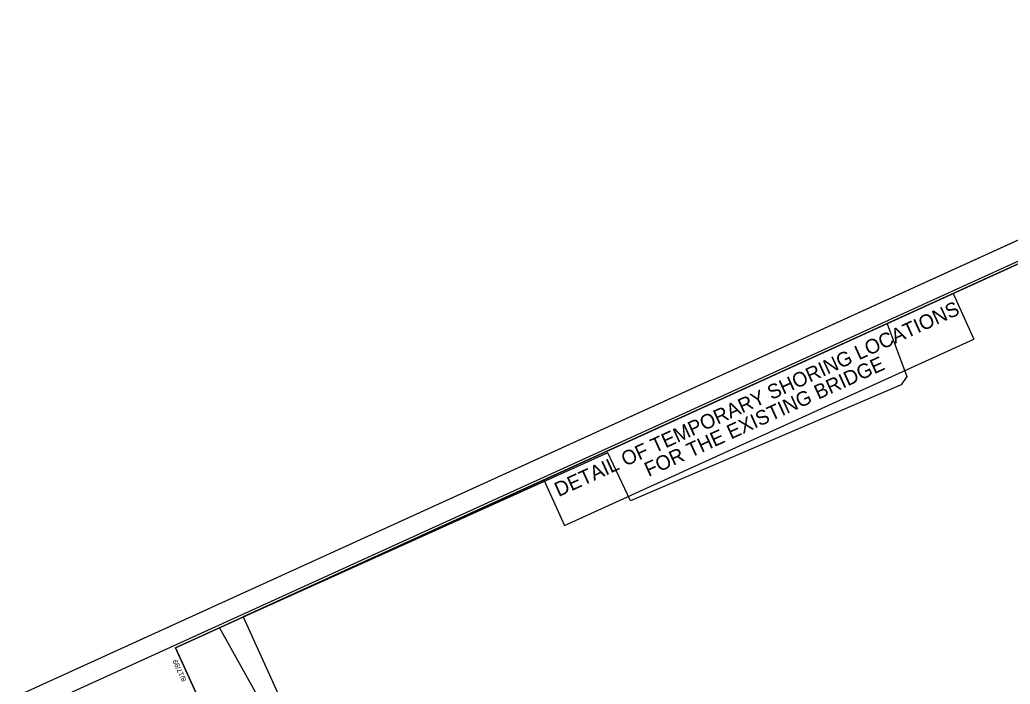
# Model space of a CAD drawing. Extents: x 2247910 to 2249896, y 662531 to 664266.
# Drawn here: x 2247910 to 2248933, y 663539 to 664226 of the extents above; entities that cross this region are included whole.
import ezdxf

# ---------------------------------------------------------------- set-up
doc = ezdxf.new("R2010")
doc.units = 0
for name, color, linetype in [('Prop Dimension', 7, 'Continuous'), ('Sheet Clip Boundary CELL', 7, 'Continuous'), ('Sheet Cutting Line CELL', 7, 'Continuous'), ('Sheet Layout Plan Border', 7, 'Continuous'), ('Sheet Plan CELL', 7, 'Continuous'), ('Sheet Plan Layout CELL', 7, 'Continuous'), ('Sheet Plot Border Inside CELL', 7, 'Continuous'), ('Sheet Plot Border Outside CELL', 7, 'Continuous')]:
    doc.layers.add(name, color=color, linetype=linetype)

msp = doc.modelspace()

# ---------------------------------------------------------------- linework, layer by layer
at = {"layer": 'Sheet Clip Boundary CELL'}
msp.add_lwpolyline([(2248241.7, 663371.1), (2248489.8, 662824.8), (2248551.2, 662641.6), (2248585.9, 662667.3), (2249638.1, 663136.9), (2249825.2, 663222.1), (2249759.4, 663344.8), (2249697.6, 663317.2), (2249673.4, 663362.4), (2249425.3, 663908.7), (2249477.5, 663985.1), (2249333.3, 663919.4), (2249245.6, 664111.9), (2248806.2, 663911.3), (2248826.4, 663857), (2248820.5, 663848.4), (2248540.8, 663728.2), (2248517.3, 663777.9), (2248115.8, 663597.1)], close=True, dxfattribs=at)
at = {"layer": 'Sheet Cutting Line CELL'}
msp.add_line((2249441.4, 664225.8), (2247909.5, 663527.8), dxfattribs=at)
at = {"layer": 'Sheet Layout Plan Border'}
msp.add_lwpolyline([(2248198.1, 663481.5), (2248575.8, 662652.8), (2249849.7, 663233.3), (2249502.1, 663996.3), (2249329.8, 663917.8), (2249242.1, 664110.3), (2248140.4, 663608.2)], close=True, dxfattribs=at)
at = {"layer": 'Sheet Plan CELL'}
for p, q in [((2248874.3, 663942.7), (2248895.8, 663895.5)), ((2248472.7, 663702.7), (2248895.8, 663895.5)), ((2248451.2, 663749.9), (2248472.7, 663702.7)), ((2248070.3, 663576.3), (2248070.3, 663576.3))]:
    msp.add_line(p, q, dxfattribs=at)
for points in [[(2249435.3, 664198.3), (2248070.3, 663576.3), (2248505.7, 662620.9), (2249870.7, 663242.8)], [(2248505.7, 662620.9), (2248070.3, 663576.3), (2249253.3, 664115.4), (2249268.8, 664081.2), (2249359.9, 664122.7), (2249406.5, 664020.3), (2249497.5, 664061.8), (2249870.7, 663242.8)]]:
    msp.add_lwpolyline(points, close=True, dxfattribs=at)
at = {"layer": 'Sheet Plan Layout CELL'}
msp.add_lwpolyline([(2248070.3, 663576.3), (2248505.7, 662620.9), (2249870.7, 663242.8), (2249523, 664005.9), (2249305.3, 663906.7), (2249217.6, 664099.1)], close=True, dxfattribs=at)
at = {"layer": 'Sheet Plot Border Inside CELL'}
msp.add_lwpolyline([(2248367.1, 662554.9), (2249883.1, 663245.8), (2249445.6, 664205.8), (2247929.6, 663514.9)], close=True, dxfattribs=at)
at = {"layer": 'Sheet Plot Border Outside CELL'}
msp.add_lwpolyline([(2248363.6, 662531.3), (2249895.5, 663229.4), (2249441.4, 664225.8), (2247909.5, 663527.8)], close=True, dxfattribs=at)

# ---------------------------------------------------------------- texts
at = {"layer": 'Prop Dimension'}
for s, p in [('DETAIL OF TEMPORARY SHORING LOCATIONS', (2248466.5, 663732.2)), ('FOR THE EXISTING BRIDGE', (2248559.5, 663752.9))]:
    msp.add_text(s, height=15, rotation=24.4979, dxfattribs=at).set_placement(p)
at = {"layer": 'Sheet Plan CELL'}
msp.add_text('8/17/99', height=5.25, rotation=114.4979, dxfattribs=at).set_placement((2248082, 663542.9))

doc.saveas('drawing.dxf')
